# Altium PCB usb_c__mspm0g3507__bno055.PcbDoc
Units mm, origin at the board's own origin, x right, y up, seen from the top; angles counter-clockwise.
Board outline 68 x 40 mm, 2 copper layers (Top, Bottom), stack 0 mm thick; 44 components, 36 nets, 224 pads, 73 vias.
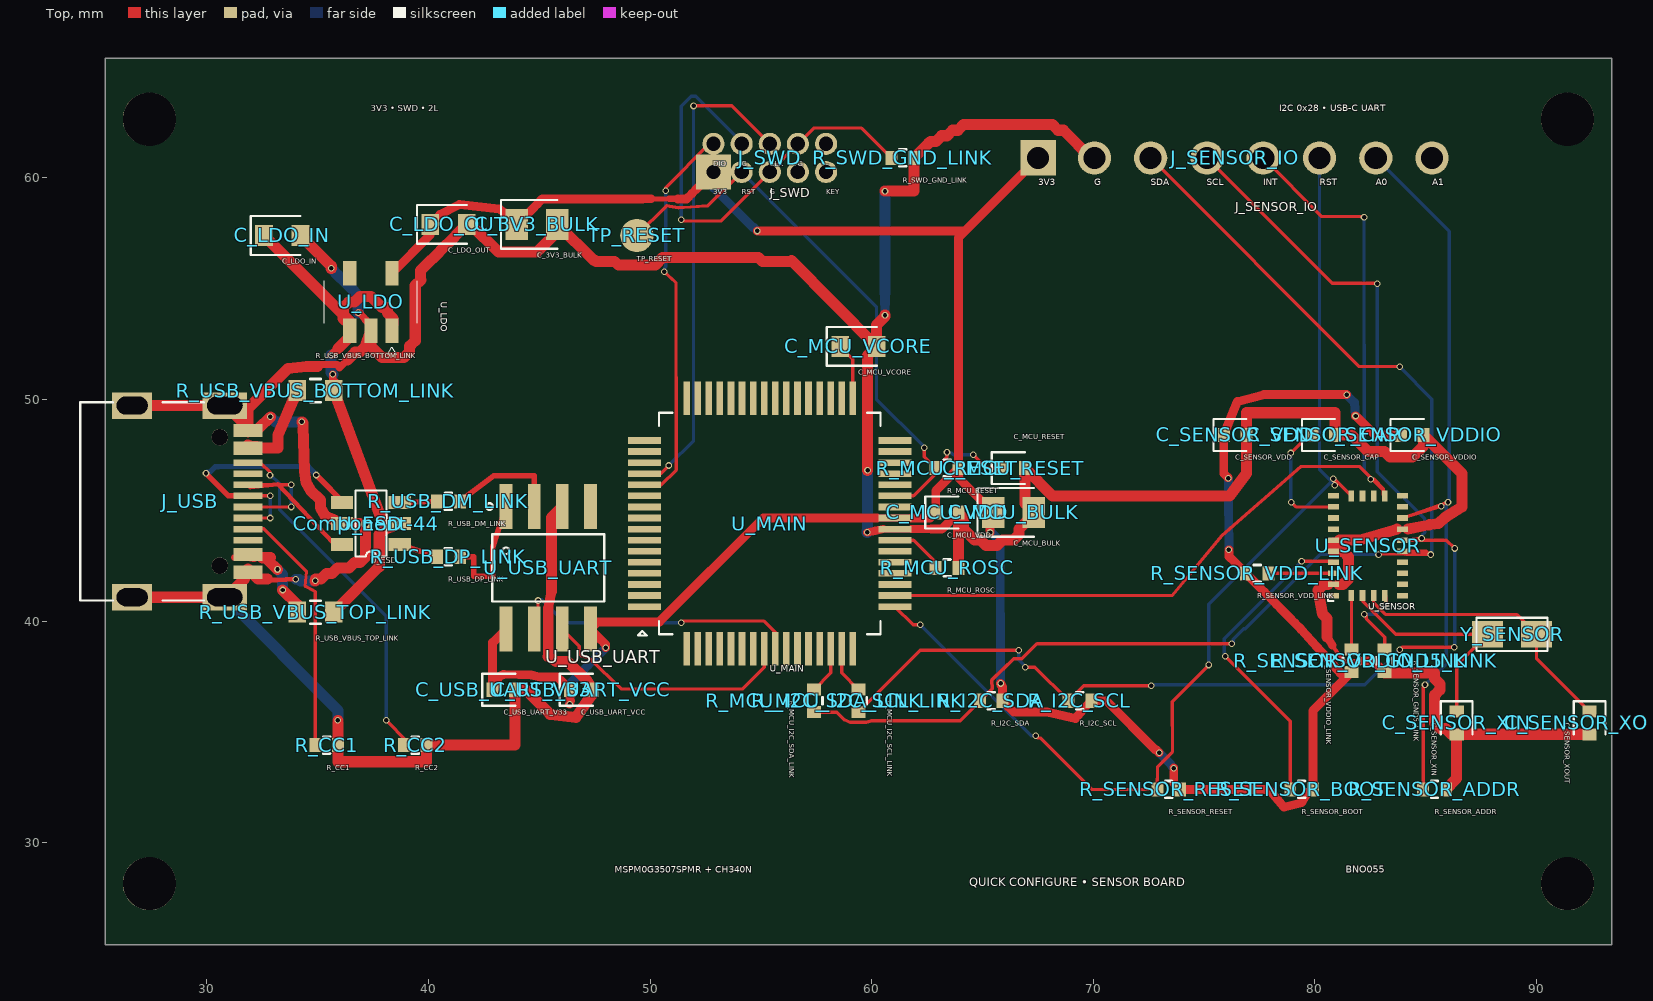
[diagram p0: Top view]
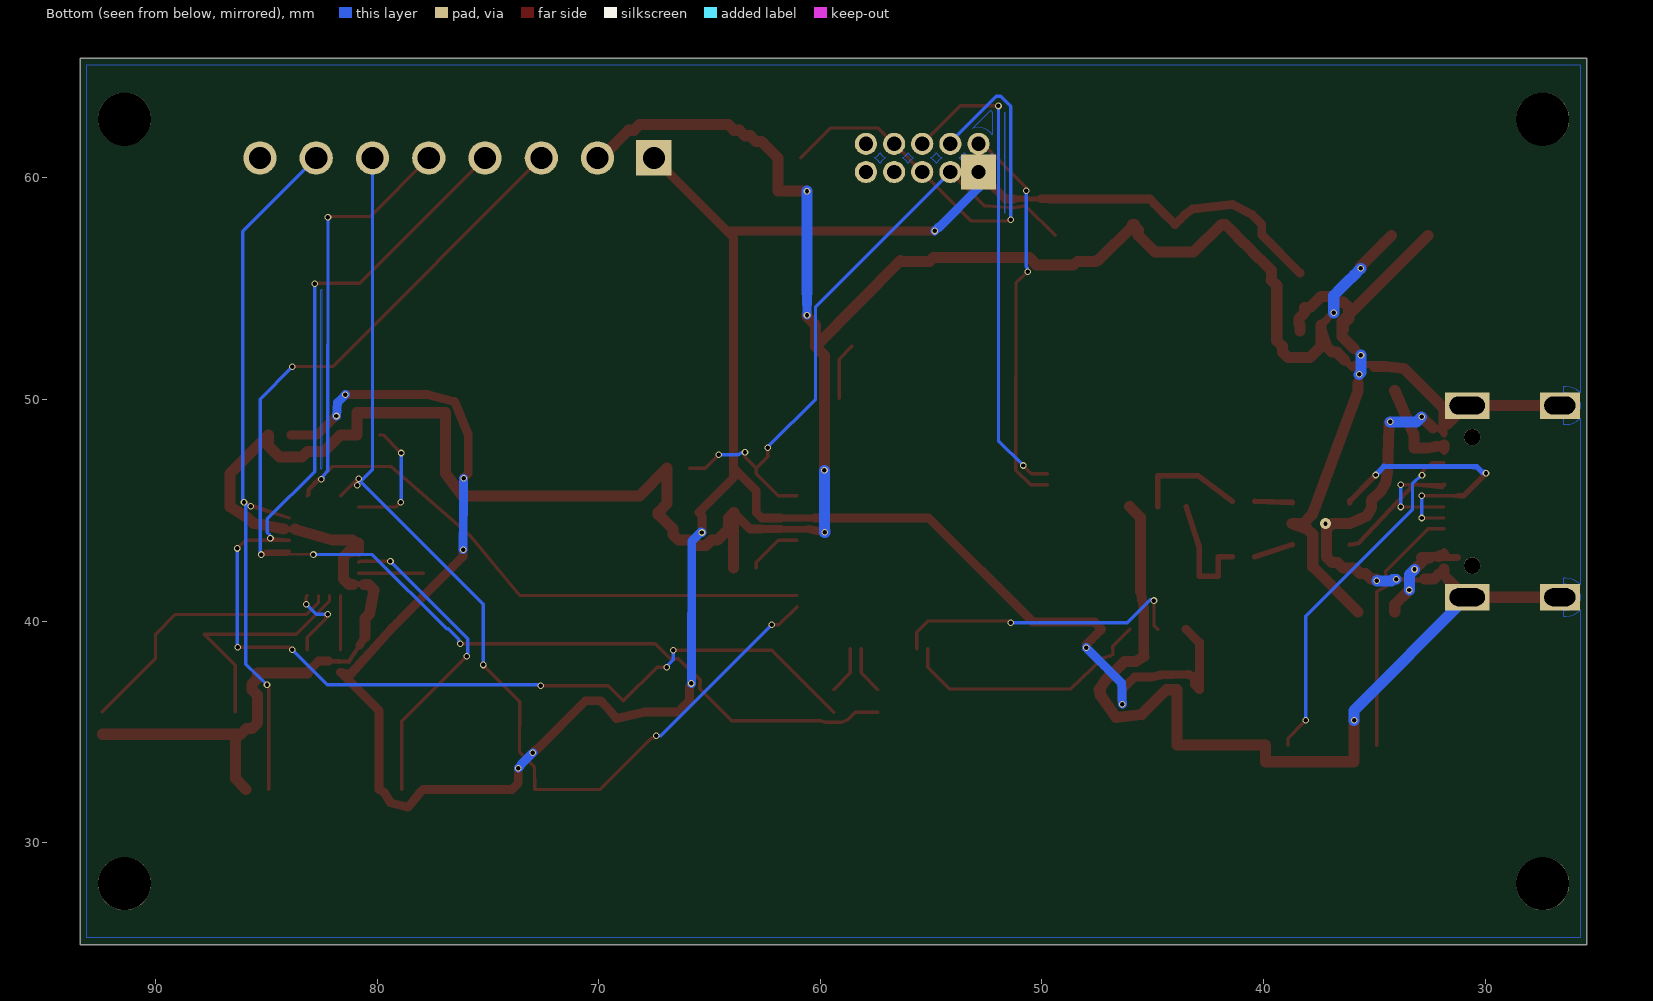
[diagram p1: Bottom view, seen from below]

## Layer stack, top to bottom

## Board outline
25.4,65.4 93.4,65.4 93.4,25.4 25.4,25.4

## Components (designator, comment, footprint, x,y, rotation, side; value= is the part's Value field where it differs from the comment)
C_3V3_BULK "" TSCIRCUIT-2.8500x1.4000mm 44.9,57.9 r0 top
C_LDO_IN "" TSCIRCUIT-2.4500x0.9500mm 33.4,57.4 r0 top
C_LDO_OUT "" TSCIRCUIT-2.4500x0.9500mm 40.9,57.9 r0 top
C_MCU_BULK "" TSCIRCUIT-2.8500x1.4000mm 66.4,44.9 r0 top
C_MCU_RESET "" TSCIRCUIT-1.5600x0.6400mm 66.4,46.9 r0 top
C_MCU_VCORE "" TSCIRCUIT-2.4500x0.9500mm 59.4,52.4 r0 top
C_MCU_VDD "" TSCIRCUIT-1.5600x0.6400mm 63.4,44.9 r0 top
C_SENSOR_CAP "" TSCIRCUIT-1.5600x0.6400mm 80.4,48.4 r0 top
C_SENSOR_VDD "" TSCIRCUIT-1.5600x0.6400mm 76.4,48.4 r0 top
C_SENSOR_VDDIO "" TSCIRCUIT-1.5600x0.6400mm 84.4,48.4 r0 top
C_SENSOR_XIN "" TSCIRCUIT-0.6400x1.5600mm 86.4,35.4 r270 top
C_SENSOR_XOUT "" TSCIRCUIT-0.6400x1.5600mm 92.4,35.4 r270 top
C_USB_UART_V33 "" TSCIRCUIT-1.5600x0.6400mm 43.4,36.9 r0 top
C_USB_UART_VCC "" TSCIRCUIT-1.5600x0.6400mm 46.9,36.9 r0 top
Component-44 "" TSCIRCUIT-0.5000x0.5000mm 37.2,44.4 r0 top
J_SENSOR_IO "" TSCIRCUIT-19.2800x1.5000mm 76.4,60.9 r0 top
J_SWD "" TSCIRCUIT-6.0800x2.2700mm 55.4,60.9 r0 top
J_USB "" TSCIRCUIT-6.7732x9.8502mm 29.112,45.4 r90 top
R_CC1 "" TSCIRCUIT-1.5600x0.6400mm 35.4,34.4 r0 top
R_CC2 "" TSCIRCUIT-1.5600x0.6400mm 39.4,34.4 r0 top
R_I2C_SCL "" TSCIRCUIT-1.5600x0.6400mm 69.4,36.4 r0 top
R_I2C_SDA "" TSCIRCUIT-1.5600x0.6400mm 65.4,36.4 r0 top
R_MCU_I2C_SCL_LINK "" TSCIRCUIT-0.6400x1.5600mm 59.4,36.4 r270 top
R_MCU_I2C_SDA_LINK "" TSCIRCUIT-0.6400x1.5600mm 57.4,36.4 r270 top
R_MCU_RESET "" TSCIRCUIT-1.5600x0.6400mm 63.4,46.9 r0 top
R_MCU_ROSC "" TSCIRCUIT-1.5600x0.6400mm 63.4,42.4 r0 top
R_SENSOR_ADDR "" TSCIRCUIT-1.5600x0.6400mm 85.4,32.4 r0 top
R_SENSOR_BOOT "" TSCIRCUIT-1.5600x0.6400mm 79.4,32.4 r0 top
R_SENSOR_GND5_LINK "" TSCIRCUIT-0.6400x1.5600mm 83.15,38.2 r270 top
R_SENSOR_RESET "" TSCIRCUIT-1.5600x0.6400mm 73.4,32.4 r0 top
R_SENSOR_VDD_LINK "" TSCIRCUIT-1.5600x0.6400mm 77.4,42.15 r0 top
R_SENSOR_VDDIO_LINK "" TSCIRCUIT-0.6400x1.5600mm 81.65,38.2 r270 top
R_SWD_GND_LINK "" TSCIRCUIT-1.5600x0.6400mm 61.4,60.9 r0 top
R_USB_DM_LINK "" TSCIRCUIT-1.5600x0.6400mm 40.9,45.4 r0 top
R_USB_DP_LINK "" TSCIRCUIT-1.5600x0.6400mm 40.9,42.9 r0 top
R_USB_VBUS_BOTTOM_LINK "" TSCIRCUIT-2.4500x0.9500mm 34.9,50.4 r0 top
R_USB_VBUS_TOP_LINK "" TSCIRCUIT-2.4500x0.9500mm 34.9,40.4 r0 top
TP_RESET "" TSCIRCUIT-1.5000x1.5000mm 49.4,57.4 r0 top
U_ESD "" TSCIRCUIT-3.6000x2.5000mm 37.4,44.4 r0 top
U_LDO "" TSCIRCUIT-2.5000x3.7000mm 37.4,54.4 r270 top
U_MAIN "" TSCIRCUIT-12.8000x12.8000mm 55.4,44.4 r0 top
U_SENSOR "" TSCIRCUIT-3.6260x4.9999mm 82.4,43.4 r0 top
U_USB_UART "" TSCIRCUIT-4.3840x7.5712mm 45.4,42.4 r0 top
Y_SENSOR "" TSCIRCUIT-3.6000x1.2000mm 88.9,39.4 r0 top

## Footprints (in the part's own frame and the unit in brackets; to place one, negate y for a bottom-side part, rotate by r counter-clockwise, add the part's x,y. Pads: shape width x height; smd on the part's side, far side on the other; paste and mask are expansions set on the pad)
TSCIRCUIT-0.5000x0.5000mm [mm]
TSCIRCUIT-0.6400x1.5600mm [mm]
  rect 0.54x0.64 smd: 1(-0.51,0) 2(0.51,0)
  silkscreen extent -0.98,-0.72 0.51,0.72
TSCIRCUIT-1.5000x1.5000mm [mm]
  round 1.5 smd: 1(0,0)
TSCIRCUIT-1.5600x0.6400mm [mm]
  rect 0.54x0.64 smd: 1(-0.51,0) 2(0.51,0)
  silkscreen extent -0.98,-0.72 0.51,0.72
TSCIRCUIT-2.4500x0.9500mm [mm]
  rect 0.8x0.95 smd: 1(-0.825,0) 2(0.825,0)
  silkscreen extent -1.42,-0.87 0.82,0.87
TSCIRCUIT-2.5000x3.7000mm [mm]
  rect 1.1x0.6 smd: 1(1.3,0.95) 2(1.3,0) 3(1.3,-0.95) 4(-1.3,-0.95) 5(-1.3,0.95)
  silkscreen extent -0.95,-2.1 2.35,2.1
TSCIRCUIT-2.8500x1.4000mm [mm]
  rect 1.025x1.4 smd: 1(-0.913,0) 2(0.913,0)
  silkscreen extent -1.62,-1.1 0.91,1.1
TSCIRCUIT-3.6000x1.2000mm [mm]
  rect 1.4x1.2 smd: 1(-1.1,0) 2(1.1,0)
  silkscreen extent -1.6,-0.75 1.6,0.75
TSCIRCUIT-3.6000x2.5000mm [mm]
  rect 1x0.6 smd: 1(-1.3,-0.95) 2(-1.3,0) 3(-1.3,0.95) 4(1.3,0.95) 5(1.3,0) 6(1.3,-0.95)
  silkscreen extent -0.7,-1.49 0.7,1.49
TSCIRCUIT-3.6260x4.9999mm [mm]
  rect 0.5x0.25 smd: 1(-1.563,-2.25) 2(-1.563,-1.75) 3(-1.563,-1.25) 4(-1.563,-0.75) 5(-1.563,-0.25) 6(-1.563,0.25) 7(-1.563,0.75) 8(-1.563,1.25) 9(-1.563,1.75) 10(-1.563,2.25) 15(1.563,2.25) 16(1.563,1.75) 17(1.563,1.25) 18(1.563,0.75) 19(1.563,0.25) 20(1.563,-0.25) 21(1.563,-0.75) 22(1.563,-1.25) 23(1.563,-1.75) 24(1.563,-2.25)
  rect 0.25x0.5 smd: 11(-0.75,2.25) 12(-0.25,2.25) 13(0.25,2.25) 14(0.75,2.25) 25(0.75,-2.25) 26(0.25,-2.25) 27(-0.25,-2.25) 28(-0.75,-2.25)
  silkscreen extent -1.81,-2.5 -1.56,-2.25
TSCIRCUIT-4.3840x7.5712mm [mm]
  rect 0.574x2.036 smd: 1(-1.905,2.768) 2(-0.635,2.768) 3(0.635,2.768) 4(1.905,2.768) 5(1.905,-2.768) 6(0.635,-2.768) 7(-0.635,-2.768) 8(-1.905,-2.768)
  silkscreen extent -2.79,-1.52 2.53,2.92
TSCIRCUIT-6.0800x2.2700mm [mm]
  rect 1.6x1.6 hole 0.65: 1(-2.54,-0.635)
  round 1 hole 0.65: 2(-2.54,0.635) 3(-1.27,0.635) 4(0,0.635) 5(1.27,0.635) 6(2.54,0.635) 7(2.54,-0.635) 8(1.27,-0.635) 9(0,-0.635) 10(-1.27,-0.635)
TSCIRCUIT-6.7732x9.8502mm [mm]
  rect 0.3x1.3 smd: 1(-3.35,-2.737) 2(-3.05,-2.737) 3(-2.55,-2.737) 4(-2.25,-2.737) 5(-1.75,-2.737) 6(-1.25,-2.737) 7(-0.75,-2.737) 8(-0.25,-2.737) 9(0.25,-2.737) 10(0.75,-2.737) 11(1.25,-2.737) 12(1.75,-2.737) 13(2.55,-2.737) 14(2.25,-2.737) 15(3.35,-2.737) 16(3.05,-2.737)
  rect 1.2x2 hole 0.8 slot 1.6 at 90 deg: 17(-4.325,-1.693) 18(4.325,-1.693)
  rect 1.2x1.8 hole 0.8 slot 1.4 at 90 deg: 19(4.325,2.487) 20(-4.325,2.487)
  round 0.75 hole 0.75 unplated: NPTH-1(-2.9,-1.468) NPTH-2(2.9,-1.468)
  silkscreen extent -4.47,-0.75 4.47,4.83
TSCIRCUIT-12.8000x12.8000mm [mm]
  rect 1.5x0.3 smd: 1(-5.65,-3.75) 2(-5.65,-3.25) 3(-5.65,-2.75) 4(-5.65,-2.25) 5(-5.65,-1.75) 6(-5.65,-1.25) 7(-5.65,-0.75) 8(-5.65,-0.25) 9(-5.65,0.25) 10(-5.65,0.75) 11(-5.65,1.25) 12(-5.65,1.75) 13(-5.65,2.25) 14(-5.65,2.75) 15(-5.65,3.25) 16(-5.65,3.75) 33(5.65,3.75) 34(5.65,3.25) 35(5.65,2.75) 36(5.65,2.25) 37(5.65,1.75) 38(5.65,1.25) 39(5.65,0.75) 40(5.65,0.25) 41(5.65,-0.25) 42(5.65,-0.75) 43(5.65,-1.25) 44(5.65,-1.75) 45(5.65,-2.25) 46(5.65,-2.75) 47(5.65,-3.25) 48(5.65,-3.75)
  rect 0.3x1.5 smd: 17(-3.75,5.65) 18(-3.25,5.65) 19(-2.75,5.65) 20(-2.25,5.65) 21(-1.75,5.65) 22(-1.25,5.65) 23(-0.75,5.65) 24(-0.25,5.65) 25(0.25,5.65) 26(0.75,5.65) 27(1.25,5.65) 28(1.75,5.65) 29(2.25,5.65) 30(2.75,5.65) 31(3.25,5.65) 32(3.75,5.65) 49(3.75,-5.65) 50(3.25,-5.65) 51(2.75,-5.65) 52(2.25,-5.65) 53(1.75,-5.65) 54(1.25,-5.65) 55(0.75,-5.65) 56(0.25,-5.65) 57(-0.25,-5.65) 58(-0.75,-5.65) 59(-1.25,-5.65) 60(-1.75,-5.65) 61(-2.25,-5.65) 62(-2.75,-5.65) 63(-3.25,-5.65) 64(-3.75,-5.65)
  silkscreen extent -5.95,-5.05 5,5
TSCIRCUIT-19.2800x1.5000mm [mm]
  rect 1.6x1.6 hole 1: 1(-8.89,0)
  round 1.5 hole 1: 2(-6.35,0) 3(-3.81,0) 4(-1.27,0) 5(1.27,0) 6(3.81,0) 7(6.35,0) 8(8.89,0)

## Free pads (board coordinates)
  round 2.4 hole 2.4 unplated: NPTH-3(27.4,28.15) NPTH-4(91.4,28.15) NPTH-5(27.4,62.65) NPTH-6(91.4,62.65)

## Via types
v1: diameter 0.3, hole 0.2, Top to Bottom, 72 vias
v2: diameter 0.5, hole 0.2, Top to Bottom, 1 vias

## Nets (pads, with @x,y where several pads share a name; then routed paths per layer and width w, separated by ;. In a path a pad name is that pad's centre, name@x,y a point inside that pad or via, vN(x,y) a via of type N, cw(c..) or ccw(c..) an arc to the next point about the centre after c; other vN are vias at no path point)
".J_SWD > .pin2 to .U_MAIN > .pin12": J_SWD.2 U_MAIN.12 | length 17.7
  Top w0.15: U_MAIN.12 50.506,46.15 51.174,46.813 51.169,55.271 v1(50.637,55.757) ; v1(50.703,59.419) 50.7,59.422 50.7,59.556 52.68,61.535 J_SWD.2
  Bottom w0.15: v1(50.637,55.757) 50.659,55.825 50.659,55.938 50.703,55.982 v1(50.703,59.419)
".J_SWD > .pin4 to .U_MAIN > .pin13": J_SWD.4 U_MAIN.13 | length 22.1
  Top w0.15: U_MAIN.13 50.471,46.65 v1(50.834,47.019) ; v1(51.96,63.247) 51.968,63.255 52.112,63.255 53.68,63.255 J_SWD.4
  Bottom w0.15: v1(50.834,47.019) 50.843,47.022 51.96,48.139 v1(51.96,63.247)
".U_MAIN > .pin42 to .R_MCU_ROSC > .pin1": R_MCU_ROSC.1 U_MAIN.42 | length 2.5
  Top w0.15: U_MAIN.42 61.889,43.65 62.89,42.649 R_MCU_ROSC.1
".U_SENSOR > .CAP to .C_SENSOR_CAP > .pin1": C_SENSOR_CAP.1 U_SENSOR.9 | length 5.5
  Top w0.15: v1(78.916,47.583) 78.96,47.627 79.733,48.4 C_SENSOR_CAP.1 ; v1(78.93,45.367) 79.147,45.15 U_SENSOR.9
  Bottom w0.15: v1(78.916,47.583) 78.916,45.583 78.916,45.381 v1(78.93,45.367)
BNO055_GND5_LOCAL: R_SENSOR_GND5_LINK.1 U_SENSOR.25 | length 3.6
  Top w0.15: v1(82.234,40.311) 82.315,40.23 82.315,40.114 83.15,39.278 R_SENSOR_GND5_LINK.1 ; U_SENSOR.25 83.214,41.086 v1(83.2,40.75)
  Bottom w0.15: v1(82.234,40.311) 82.759,40.311 83.161,40.713 83.178,40.713 v1(83.2,40.75)
BNO055_VDD_LOCAL: R_SENSOR_VDD_LINK.2 U_SENSOR.3 | length 2.9
  Top w0.15: R_SENSOR_VDD_LINK.2 U_SENSOR.3@80.837,42.15
BNO055_VDDIO_LOCAL: R_SENSOR_VDDIO_LINK.1 U_SENSOR.28 | length 2.4
  Top w0.15: R_SENSOR_VDDIO_LINK.1 U_SENSOR.28
GND: C_3V3_BULK.2 C_LDO_IN.2 C_LDO_OUT.2 C_MCU_BULK.2 C_MCU_RESET.2 C_MCU_VCORE.2 C_MCU_VDD.2 C_SENSOR_CAP.2 C_SENSOR_VDD.2 C_SENSOR_VDDIO.2 C_SENSOR_XIN.2 C_SENSOR_XOUT.2 C_USB_UART_V33.2 C_USB_UART_VCC.2 J_SENSOR_IO.2 J_USB.1 J_USB.2 J_USB.15 J_USB.16 J_USB.17 J_USB.18 J_USB.19 J_USB.20 R_CC1.2 R_CC2.2 R_MCU_ROSC.2 R_SENSOR_ADDR.2 R_SENSOR_GND5_LINK.2 R_SWD_GND_LINK.2 U_ESD.2 U_LDO.2 U_MAIN.41 U_SENSOR.2 U_SENSOR.5 U_SENSOR.6 U_SENSOR.18 U_USB_UART.3 | length 210.6
  Top w0.188: 80.788,38.91 81.032,38.54 81.275,38.17
  Top w0.2: 81.275,38.17 81.73,38.18
  Top w0.225: 32.729,41.888 32.7,41.85 33.133,41.863 33.567,41.875 v1(34,41.888) ; 81.73,38.18 82.185,38.19
  Top w0.25: U_SENSOR.2@80.587,41.65 U_SENSOR.2 U_SENSOR.2@81.087,41.65 ; U_SENSOR.5 U_SENSOR.5@81.087,43.15 ; 80.837,43.525 U_SENSOR.6 80.931,43.65 81.024,43.65 81.087,43.65 81.118,43.65 ; U_SENSOR.18@83.714,44.15 U_SENSOR.18 ; U_SENSOR.18 U_SENSOR.18@84.15,44.15
  Top w0.275: J_USB.2 J_USB.1@32.077,42.119 ; J_USB.16 J_USB.15@32.103,48.704
  Top w0.3: J_USB.1@31.699,41.9 J_USB.1 J_USB.1@31.849,42.2 ; J_USB.15@31.699,48.9 J_USB.15 ; J_USB.16@31.849,48.6 J_USB.15 ; J_USB.15@31.849,48.9 J_USB.15 ; J_USB.15@32.103,48.704 J_USB.15@32.355,48.704 ; U_MAIN.41@60.525,44.15 60.788,44.15 U_MAIN.41 61.144,44.15 61.238,44.15 61.331,44.15 61.425,44.15 61.519,44.15 61.613,44.15 61.706,44.15 61.8,44.15
  Top w0.325: J_USB.16 J_USB.16@31.849,48.6 ; 35.103,51.572 35.494,51.572 35.884,51.572 35.987,51.435 36.34,51.789 ; v1(36.828,53.91) 36.9,53.916 U_LDO.2@37.157,53.601
  Top w0.339: U_SENSOR.18@84.15,44.15 84.213,44.162
  Top w0.35: 34.978,51.484 35.103,51.572 ; U_LDO.2@37.157,53.601 U_LDO.2@37.4,53.358
  Top w0.375: v1(59.8,44) 60.163,44.075 U_MAIN.41@60.525,44.15 ; 61.8,44.15 62.253,44.15 62.707,44.15 ; 80.544,39.28 80.788,38.91
  Top w0.4: 36.6,44.4 37.2,44.4 ; 62.707,44.15 63.16,44.15 63.41,44.4 63.66,44.65 C_MCU_VDD.2 ; 82.185,38.19 82.64,38.2 82.895,37.945 R_SENSOR_GND5_LINK.2
  Top w0.45: 45.4,40.588 45.473,40.959 45.545,41.331
  Top w0.475: 45.4,38.4 45.4,38.837 45.4,39.275 45.4,39.713 45.4,40.15 45.4,40.588
  Top w0.5: J_USB.20 J_USB.17 ; J_USB.19 J_USB.18 ; J_USB.17 30.874,41.075 31.474,41.675 31.699,41.9 ; J_USB.18 30.874,49.725 31.474,49.125 31.699,48.9 ; J_USB.1@31.849,42.2 J_USB.2 ; 31.849,48.9 31.849,49.599 33.65,51.4 34.494,51.482 34.978,51.484 ; J_USB.1@32.077,42.119 32.305,41.888 32.729,41.888 ; J_USB.15@32.355,48.704 v1(32.863,49.212) ; C_LDO_IN.2 34.571,57.054 34.917,56.708 35.263,56.362 35.609,56.016 v1(35.609,55.917) ; v1(34.284,48.989) 34.331,48.942 34.331,48.807 34.4,46.775 34.462,46.275 34.681,45.892 35.119,45.455 35.119,45.127 35.338,44.744 35.719,44.572 U_ESD.2 36.9,44.4 37.15,44.15 37.15,42.9 36.9,42.65 36.65,42.65 36.4,42.4 35.9,42.4 35.65,42.15 35.4,42.15 35.15,41.9 34.9,41.9 34.9,41.832 v1(34.885,41.817) ; v1(35.91,35.52) 35.91,35.4 R_CC1.2 35.91,33.65 39.91,33.65 R_CC2.2 43.91,34.4 C_USB_UART_V33.2 44.385,36.9 45.495,35.79 46.65,35.65 47.364,36.666 47.364,36.854 C_USB_UART_VCC.2 47.15,37.306 46.275,38.181 45.75,38.181 45.4,38.4 ; 36.34,51.789 36.694,52.142 36.9,52.15 37.15,52.4 U_LDO.2 ; U_LDO.2@37.4,53.358 U_LDO.2 ; 45.545,41.331 45.545,41.81 45.545,42.288 45.545,42.766 45.545,43.244 45.545,43.722 45.545,44.2 45.545,44.678 45.79,44.923 U_USB_UART.3 ; v1(59.813,46.799) 59.816,46.802 59.816,46.82 59.816,47.29 59.816,47.76 59.816,48.23 59.816,48.7 59.816,49.17 59.816,49.64 59.816,50.11 59.816,50.58 59.816,51.05 59.816,51.521 59.816,51.991 60.02,52.195 C_MCU_VCORE.2 ; v1(60.6,53.8) 60.6,53.744 60.413,53.557 60.225,53.369 60.225,52.885 C_MCU_VCORE.2 ; v1(60.6,59.4) 61.91,59.4 R_SWD_GND_LINK.2 62.241,61.231 62.571,61.561 62.65,61.64 62.65,61.65 62.9,61.65 63.15,61.9 63.4,61.9 63.65,62.15 63.9,62.15 64.15,62.4 68.15,62.4 68.4,62.15 68.65,62.15 69.9,60.9 J_SENSOR_IO.2 ; R_MCU_ROSC.2 C_MCU_VDD.2 63.9,44.9 64.15,44.65 64.15,44.15 64.65,43.65 64.9,43.65 65.15,43.4 65.65,43.4 65.9,43.65 66.4,43.65 66.65,43.9 66.65,44.15 67.312,44.813 C_MCU_BULK.2 66.91,45.303 C_MCU_RESET.2 68.16,45.65 76.15,45.65 76.919,46.663 76.917,47.097 76.915,47.531 76.912,47.966 C_SENSOR_VDD.2 76.91,49.4 80.91,49.4 C_SENSOR_CAP.2 81.65,48.4 82.4,47.65 83.15,47.65 83.4,47.4 84.4,47.4 84.91,47.91 C_SENSOR_VDDIO.2 86.65,46.66 86.65,45.15 85.885,44.676 85.589,44.411 85.183,44.345 84.213,44.162 ; 80.544,39.28 80.544,40.111 80.336,40.318 80.15,41.4 80.4,41.65 80.587,41.65 ; U_SENSOR.5 80.837,43.275 80.837,43.525 ; 81.087,41.65 81.275,41.65 81.525,41.9 81.525,42.9 81.275,43.15 81.087,43.15 ; 81.118,43.65 81.212,43.65 81.306,43.65 81.399,43.65 81.493,43.65 81.587,43.65 81.994,43.65 U_SENSOR.18@83.713,44.149 ; R_SENSOR_GND5_LINK.2 83.15,37.65 85.4,37.65 85.4,37.4 85.65,37.15 85.65,36.9 85.4,36.65 85.4,35.4 85.65,35.15 85.9,35.15 86.16,34.89 C_SENSOR_XIN.2 ; R_SENSOR_ADDR.2 86.4,32.89 C_SENSOR_XIN.2 ; C_SENSOR_XOUT.2 C_SENSOR_XIN.2 ; U_LDO.2 37.4,52.4 37.9,51.9 38.9,51.9 39.15,52.15 39.15,52.4 39.4,52.65 39.4,55.15 39.65,55.4 39.65,55.39 39.635,55.375 39.635,55.81 39.983,56.158 40.332,56.507 40.68,56.855 41.028,57.203 41.377,57.552 C_LDO_OUT.2 41.9,57.9 43.15,56.65 44.9,56.65 45.65,57.4 45.65,57.65 45.9,57.9 C_3V3_BULK.2 47.465,56.277 47.523,56.277 47.567,56.233 48.4,56.233 48.567,56.067 50.233,56.067 50.567,56.4 54.9,56.4 55.067,56.233 56.4,56.233 56.378,56.256 56.378,56.264 C_MCU_VCORE.2
  Bottom w0.4: v1(60.6,53.8) 60.6,54.291
  Bottom w0.437: 60.6,54.291 60.6,54.781
  Bottom w0.45: v1(34,41.888) v1@34.015,41.879
  Bottom w0.475: v1@34.015,41.879 34.161,41.879
  Bottom w0.5: J_USB.17 35.91,35.971 v1(35.91,35.52) ; v1(32.863,49.212) 32.867,49.208 32.876,49.208 33.095,48.989 33.491,48.989 33.888,48.989 v1(34.284,48.989) ; 34.161,41.879 34.226,41.814 34.555,41.816 v1(34.885,41.817) ; v1(35.609,55.917) 35.619,55.907 35.921,55.605 36.224,55.302 36.526,55 36.828,54.698 36.828,54.304 v1(36.828,53.91) ; v1(59.8,44) 59.8,44.056 59.813,44.069 59.813,44.524 59.813,44.979 59.813,45.434 59.813,45.889 59.813,46.344 v1(59.813,46.799) ; 60.6,54.781 60.6,55.272 60.6,55.763 60.6,56.254 60.6,56.744 60.6,57.235 60.6,57.726 60.6,58.216 60.6,58.707 60.6,59.198 v1(60.6,59.4)
MAIN_RESET: C_MCU_RESET.1 J_SWD.10 R_MCU_RESET.1 TP_RESET.1 U_MAIN.38 | length 29.1
  Top w0.15: TP_RESET.1 50.744,58.744 51.277,58.653 51.833,58.682 52.593,58.744 52.609,58.744 J_SWD.10 ; U_MAIN.38 61.889,45.65 62.89,46.651 R_MCU_RESET.1 ; v1(62.378,47.818) 62.378,47.412 R_MCU_RESET.1 ; v1(63.4,47.62) 63.4,47.41 R_MCU_RESET.1 ; v1(64.583,47.507) 64.625,47.465 65.19,46.9 C_MCU_RESET.1
  Bottom w0.15: J_SWD.10 60.216,54.179 60.216,50.036 60.216,50.015 62.32,47.911 62.32,47.876 v1(62.378,47.818) ; v1(63.4,47.62) 63.438,47.582 63.615,47.582 63.69,47.507 v1(64.583,47.507)
MCU_I2C_SCL_LOCAL: R_MCU_I2C_SCL_LINK.1 U_MAIN.50 | length 2.2
  Top w0.15: U_MAIN.50 58.65,37.66 R_MCU_I2C_SCL_LINK.1
MCU_I2C_SDA_LOCAL: R_MCU_I2C_SDA_LINK.1 U_MAIN.51 | length 2.2
  Top w0.15: R_MCU_I2C_SDA_LINK.1 58.15,37.66 U_MAIN.51
MSPM0_VCORE: C_MCU_VCORE.1 U_MAIN.32 | length 2.6
  Top w0.15: C_MCU_VCORE.1 59.15,51.825 U_MAIN.32
SENSOR_ADDR0: J_SENSOR_IO.7 R_SENSOR_ADDR.1 U_SENSOR.17 | length 34.5
  Top w0.15: R_SENSOR_ADDR.1 84.89,37.005 84.992,37.107 v1(84.972,37.122) ; v1(85.7,45.175) U_SENSOR.17 v1(86.008,45.362)
  Bottom w0.15: J_SENSOR_IO.7 86.067,57.583 86.067,45.496 86.067,45.421 v1(86.008,45.362) ; v1(84.972,37.122) 85.929,38.044 85.929,45.241 85.929,45.283 v1(85.7,45.175)
SENSOR_ADDR1: J_SENSOR_IO.8
SENSOR_BOOT: R_SENSOR_BOOT.1 U_SENSOR.4 | length 14.4
  Top w0.15: v1(75.961,38.418) 76.117,38.262 76.117,38.251 78.89,35.478 R_SENSOR_BOOT.1 ; v1(79.4,42.7) 80.787,42.7 U_SENSOR.4
  Bottom w0.15: v1(75.961,38.418) 75.913,38.464 75.91,39.148 75.915,39.198 79.385,42.669 79.385,42.685 v1(79.4,42.7)
SENSOR_INT: J_SENSOR_IO.5 U_MAIN.47 U_SENSOR.14 | length 43.9
  Top w0.15: U_MAIN.47 73.557,41.15 75.796,43.856 79.386,46.978 82.013,46.978 83.118,45.873 83.118,45.682 U_SENSOR.14 83.094,45.706 83.094,45.974 82.674,46.394 v1(82.52,46.394) ; J_SENSOR_IO.5 80.314,58.256 82.075,58.256 82.177,58.256 v1(82.22,58.216)
  Bottom w0.15: v1(82.22,58.216) 82.23,46.777 82.436,46.558 82.436,46.478 v1(82.52,46.394)
SENSOR_RESET: J_SENSOR_IO.6 R_SENSOR_RESET.1 U_MAIN.48 U_SENSOR.11 | length 50.2
  Top w0.15: U_MAIN.48 61.871,39.829 v1(62.189,39.829) ; v1(67.4,34.82) 67.495,34.725 67.603,34.725 69.929,32.4 R_SENSOR_RESET.1 72.899,33.431 73.578,34.109 73.568,36.363 75.163,37.958 75.163,37.964 v1(75.218,38.019) ; v1(80.833,46.422) v1@80.878,46.422 ; v1(80.9,46.125) v1@80.878,46.422 ; v1@80.878,46.422 U_SENSOR.11 v1@80.878,46.422
  Bottom w0.15: v1(62.189,39.829) 62.216,39.802 67.198,34.82 v1(67.4,34.82) ; v1(75.218,38.019) 75.218,40.76 80.79,46.332 80.79,46.379 v1(80.833,46.422) ; J_SENSOR_IO.6 80.21,46.823 80.686,46.347 80.758,46.347 v1(80.9,46.125)
SENSOR_SCL: J_SENSOR_IO.4 R_I2C_SCL.1 R_MCU_I2C_SCL_LINK.2 U_SENSOR.19 | length 60.6
  Top w0.15: R_MCU_I2C_SCL_LINK.2 62.192,38.682 66.616,38.682 66.63,38.682 v1(66.632,38.68) ; v1(66.924,37.92) 67.37,37.92 R_I2C_SCL.1 69.577,37.087 v1(72.609,37.087) ; J_SENSOR_IO.4 80.782,55.248 82.789,55.248 v1(82.817,55.22) ; v1(83.825,38.7) 83.833,38.7 83.943,38.81 v1(86.285,38.81) ; v1(84.815,43.741) U_SENSOR.19 85.937,43.65 86.309,43.278 v1(86.311,43.276)
  Bottom w0.15: v1(66.632,38.68) 66.632,38.257 66.862,38.026 66.862,37.982 v1(66.924,37.92) ; v1(72.609,37.087) 72.642,37.12 72.733,37.12 82.245,37.12 v1(83.825,38.7) ; v1(82.817,55.22) 82.817,46.741 84.953,44.606 84.953,43.994 84.856,43.897 84.856,43.811 v1(84.815,43.741) ; v1(86.285,38.81) 86.311,38.836 86.311,39.026 v1(86.311,43.276)
SENSOR_SDA: J_SENSOR_IO.3 R_I2C_SDA.1 R_MCU_I2C_SDA_LINK.2 U_SENSOR.20 | length 58.3
  Top w0.15: R_MCU_I2C_SDA_LINK.2 58.417,35.89 58.758,35.548 59.032,35.43 59.3,35.43 59.55,35.429 59.764,35.43 60,35.502 59.987,35.502 63.992,35.502 R_I2C_SDA.1 65.436,36.947 65.418,37.339 66.414,38.304 66.778,38.301 67.458,38.981 v1(76.25,38.981) ; J_SENSOR_IO.3 82.004,51.486 83.765,51.486 83.808,51.486 v1(83.824,51.47) ; v1(82.875,43) 85.2,43.025 85.161,43.025 85.036,43.15 U_SENSOR.20 84.112,43.001 v1(85.224,43.001)
  Bottom w0.15: v1(76.25,38.981) 76.311,39.048 76.311,39.175 76.786,39.65 76.864,39.65 80.215,43.001 v1(82.875,43) ; v1(83.824,51.47) 85.274,50.02 85.274,43.149 85.274,43.051 v1(85.224,43.001)
SENSOR_XIN: C_SENSOR_XIN.1 U_SENSOR.27 Y_SENSOR.1 | length 10.6
  Top w0.15: U_SENSOR.27 82.154,41.146 82.154,40.902 83.656,39.4 Y_SENSOR.1 86.4,38 C_SENSOR_XIN.1
SENSOR_XOUT: C_SENSOR_XOUT.1 U_SENSOR.26 Y_SENSOR.2 | length 12.7
  Top w0.15: U_SENSOR.26 82.649,40.836 83.187,40.298 89.101,40.299 Y_SENSOR.2 90,38.31 C_SENSOR_XOUT.1
swd-ground-1-to-2: J_SWD.3 J_SWD.5 J_SWD.9 R_SWD_GND_LINK.1 | length 20.8
  Top w0.15: v1(51.402,58.115) 51.464,58.053 51.566,58.053 53.188,58.053 J_SWD.9 J_SWD.5 57.382,62.247 59.375,62.247 59.543,62.247 R_SWD_GND_LINK.1
  Bottom w0.15: v1(51.402,58.115) 51.402,63.235 51.847,63.679 52.066,63.679 54.011,61.734 54.011,61.654 J_SWD.3
UART_MSP_RX: U_MAIN.57 U_USB_UART.6 | length 11.7
  Top w0.15: U_USB_UART.6 46.807,38.86 46.791,38.493 46.894,38.439 47.248,38.324 48.711,36.929 54.165,36.929 55.15,37.914 U_MAIN.57
UART_MSP_TX: U_MAIN.56 U_USB_UART.7 | length 13.5
  Top w0.15: U_USB_UART.7 44.943,39.81 v1(44.943,40.924) ; v1(51.408,39.926) 51.413,39.931 51.421,39.931 51.491,40 55.142,40 55.65,39.492 U_MAIN.56
  Bottom w0.15: v1(44.943,40.924) 44.994,40.975 45.094,40.975 46.144,39.926 v1(51.408,39.926)
usb-dm-device: R_USB_DM_LINK.1 U_ESD.4 | length 1.7
  Top w0.25: U_ESD.4 R_USB_DM_LINK.1
usb-dm-port-tie: J_USB.7 J_USB.9 U_ESD.3 | length 12.4
  Top w0.15: J_USB.9@31.349,45.65 31.38,45.65 31.474,45.65 31.568,45.65 31.662,45.65 31.615,45.65 J_USB.9 v1(32.85,45.65) ; J_USB.7 v1(32.85,44.65)
  Top w0.175: J_USB.9@31.287,45.65 J_USB.9@31.349,45.65
  Top w0.212: 31.193,45.65 J_USB.9@31.287,45.65
  Top w0.25: v1(29.956,46.662) 30.968,45.65 31.099,45.65 31.193,45.65 ; v1(34.932,46.591) 35.09,46.433 ; 35.09,46.432 36.1,45.422 U_ESD.3
  Bottom w0.15: v1(32.85,44.65) v1(32.85,45.65)
  Bottom w0.25: v1(29.956,46.662) 30.004,46.71 30.118,46.71 30.365,46.957 30.515,46.972 34.566,46.978 v1(34.932,46.591)
usb-dm-uart: R_USB_DM_LINK.2 U_USB_UART.2 | length 5.1
  Top w0.25: R_USB_DM_LINK.2 42.95,46.55 44.765,46.55 U_USB_UART.2
usb-dp-device: R_USB_DP_LINK.1 U_ESD.6 | length 1.8
  Top w0.25: U_ESD.6 R_USB_DP_LINK.1
usb-dp-port-tie: J_USB.8 J_USB.10 U_ESD.1 | length 10.4
  Top w0.15: J_USB.8 v1(33.8,45.15) ; J_USB.10 v1(33.8,46.15)
  Top w0.2: J_USB.10 31.954,46.045 33.191,46.179 35.713,43.512 U_ESD.1
  Bottom w0.15: v1(33.8,45.15) v1(33.8,46.15)
usb-dp-uart: R_USB_DP_LINK.2 U_USB_UART.1 | length 5.6
  Top w0.25: R_USB_DP_LINK.2 42.05,42.9 42.05,42.03 42.9,42.03 42.9,43.35 U_USB_UART.1
USB_CC1: J_USB.6 R_CC1.1 | length 11.6
  Top w0.15: J_USB.6 31.861,44.162 32.57,44.162 34.49,42.242 34.425,41.575 34.889,41.333 R_CC1.1
USB_CC2: J_USB.12 R_CC2.1 | length 16
  Top w0.15: J_USB.12 32.416,47.151 32.845,46.722 v1(32.844,46.586) ; v1(38.09,35.52) 38.232,35.378 38.89,34.72 R_CC2.1
  Bottom w0.15: v1(32.844,46.586) 32.867,46.6 33.276,46.191 33.276,45.024 38.09,40.21 v1(38.09,35.52)
USB_VBUS_BOTTOM_LOCAL: J_USB.13 J_USB.14 R_USB_VBUS_BOTTOM_LINK.1 | length 4.4
  Top w0.3: J_USB.14 J_USB.14@31.849,47.8
  Top w0.45: J_USB.13 J_USB.13@32.225,47.875
  Top w0.475: J_USB.13@31.849,47.8 J_USB.13
  Top w0.5: J_USB.13@32.225,47.875 32.6,47.8 33.2,47.8 33.2,48.4 R_USB_VBUS_BOTTOM_LINK.1
USB_VBUS_TOP_LOCAL: J_USB.3 J_USB.4 R_USB_VBUS_TOP_LINK.1 | length 7.1
  Top w0.3: J_USB.4 31.849,43 J_USB.3 31.834,42.865 31.24,42.865 31.646,42.865 32.052,42.865 32.458,42.865 J_USB.3@32.499,42.865 ; J_USB.3@32.125,42.904 32.224,42.85 32.349,42.85 32.474,42.85 J_USB.3@32.499,42.85
  Top w0.423: J_USB.3@31.999,42.948 32.432,42.907 32.864,42.865
  Top w0.5: J_USB.3@31.999,42.948 J_USB.3@32.125,42.904 ; 32.499,42.85 32.599,42.85 32.651,42.85 32.703,42.798 32.791,42.71 v1(33.185,42.328) ; 32.499,42.865 32.864,42.865 ; v1(33.415,41.402) 33.44,41.377 34.075,40.742 R_USB_VBUS_TOP_LINK.1
  Bottom w0.5: v1(33.185,42.328) 33.415,42.098 v1(33.415,41.402)
VBUS5: C_LDO_IN.1 R_USB_VBUS_BOTTOM_LINK.2 R_USB_VBUS_TOP_LINK.2 U_ESD.5 U_LDO.1 U_LDO.3 | length 26.2
  Top w0.325: v1(35.6,52) v1@35.633,52.033 ; v1(35.68,51.136) 35.68,50.79 R_USB_VBUS_BOTTOM_LINK.2@35.725,50.745
  Top w0.375: v1@35.633,52.033 35.905,52.305
  Top w0.5: C_LDO_IN.1 36.45,53.525 U_LDO.3 ; R_USB_VBUS_TOP_LINK.2 37.775,42.45 37.775,43.9 38.025,44.15 U_ESD.5 38.2,44.4 37.8,44.8 R_USB_VBUS_BOTTOM_LINK.2 R_USB_VBUS_BOTTOM_LINK.2@35.725,50.745 ; 35.905,52.305 36.178,52.578 36.45,52.85 U_LDO.3 ; U_LDO.1 38.35,53.35 38.4,53.4 38.4,53.65 38.15,53.9 38.15,54.15 37.9,54.15 37.4,54.65 36.9,54.65 36.65,54.4 36.4,54.4 36.15,54.15 36.15,53.65 36.4,53.4 36.4,53.15 U_LDO.3
  Bottom w0.5: v1(35.6,52) 35.6,51.216 v1(35.68,51.136)
VCC_3V3: C_3V3_BULK.1 C_LDO_OUT.1 C_MCU_BULK.1 C_MCU_VDD.1 C_SENSOR_VDD.1 C_SENSOR_VDDIO.1 C_USB_UART_V33.1 C_USB_UART_VCC.1 J_SENSOR_IO.1 J_SWD.1 R_I2C_SCL.2 R_I2C_SDA.2 R_MCU_RESET.2 R_SENSOR_BOOT.2 R_SENSOR_RESET.2 R_SENSOR_VDD_LINK.1 R_SENSOR_VDDIO_LINK.2 U_LDO.5 U_MAIN.40 U_USB_UART.5 U_USB_UART.8 | length 141
  Top w0.225: 50.052,59.052 50.451,59.052 50.85,59.052
  Top w0.288: 50.85,59.052 51.249,59.052
  Top w0.3: 60.25,44.65 60.3,44.65 60.35,44.65 60.45,44.65 60.55,44.65 60.65,44.65 60.75,44.65 60.85,44.65 60.95,44.65 U_MAIN.40 61.15,44.65 61.25,44.65 61.35,44.65 61.45,44.65 61.55,44.65 61.65,44.65 61.75,44.65 61.8,44.65
  Top w0.337: v1@76.074,46.466 v1(76.098,46.442)
  Top w0.387: 49.654,59.052 50.052,59.052
  Top w0.4: U_LDO.5 40.075,57.425 C_LDO_OUT.1 40.296,58.122 40.518,58.343 41.4,58.8 43.2,58.6 43.545,58.343 43.766,58.121 C_3V3_BULK.1 44.218,58.13 44.449,58.361 44.679,58.591 44.91,58.822 45.14,59.052 45.485,59.052 45.829,59.052 46.174,59.052 46.518,59.052 46.863,59.052 47.261,59.052 47.66,59.052 48.059,59.052 48.458,59.052 48.856,59.052 49.255,59.052 49.654,59.052 ; U_USB_UART.8 42.89,39.027 C_USB_UART_V33.1 43.126,37.136 43.126,37.47 43.4,37.6 44.638,37.564 45.05,37.47 45.435,37.47 45.82,37.47 46.01,37.28 46.2,37.09 C_USB_UART_VCC.1 46.39,36.657 46.39,36.414 46.4,36.404 v1(46.369,36.243) ; v1(48,38.8) 48,38.937 47.768,39.169 47.537,39.4 U_USB_UART.5 47.633,39.96 50.419,39.96 55.108,44.65 60.25,44.65 ; 51.249,59.052 51.647,59.052 51.89,59.295 52.132,59.537 52.375,59.78 52.617,60.022 J_SWD.1 ; v1(54.833,57.605) 64.215,57.605 J_SENSOR_IO.1 63.91,57.3 R_MCU_RESET.2 ; 61.8,44.65 61.85,44.65 62.64,44.65 C_MCU_VDD.1 62.89,45.88 R_MCU_RESET.2 ; v1(65.341,43.997) 65.335,44.747 C_MCU_BULK.1 63.91,46.478 R_MCU_RESET.2 ; v1(65.818,37.183) 65.83,37.17 65.826,37.115 65.91,37.032 R_I2C_SDA.2 66.16,36.149 66.409,35.897 66.784,35.896 67.16,35.895 67.535,35.894 67.91,35.892 69.2,35.6 69.66,36.144 R_I2C_SCL.2 70.596,36.4 72.824,34.172 72.854,34.172 v1(72.971,34.055) ; v1(73.631,33.364) 73.631,32.679 R_SENSOR_RESET.2 74.274,32.4 74.638,32.4 75.002,32.4 75.366,32.4 75.73,32.4 76.094,32.4 76.458,32.4 76.821,32.4 77.185,32.4 77.549,32.4 77.913,32.4 78.113,32.199 78.6,31.6 79.4,31.8 79.655,32.24 R_SENSOR_BOOT.2 79.91,35.95 R_SENSOR_VDDIO_LINK.2 81.2,37.6 79.382,39.625 79.105,39.905 78.828,40.186 78.551,40.466 78.274,40.747 77.998,41.028 77.721,41.308 77.444,41.589 77.167,41.869 R_SENSOR_VDD_LINK.1 76.633,42.407 76.377,42.663 76.12,42.92 v1(76.12,43.22) ; v1@76.074,46.466 76.074,46.476 75.89,46.661 75.89,47.008 75.89,47.356 75.89,47.704 75.89,48.052 C_SENSOR_VDD.1 76.5,49.9 77.707,50.217 v1(81.433,50.217) ; v1(81.838,49.253) 81.95,49.157 81.953,49.157 82.71,48.4 C_SENSOR_VDDIO.1
  Bottom w0.4: v1(46.369,36.243) 46.379,36.562 46.39,36.881 46.4,37.2 46.665,37.465 46.93,37.73 47.195,37.995 47.459,38.259 47.724,38.524 47.989,38.789 v1(48,38.8) ; J_SWD.1 52.86,59.547 54.65,57.757 54.681,57.757 v1(54.833,57.605) ; v1(65.341,43.997) 65.378,44.017 65.378,44.024 65.8,43.602 v1(65.818,37.183) ; v1(72.971,34.055) 72.992,34.036 73.518,33.51 73.518,33.477 v1(73.631,33.364) ; v1(76.098,46.442) 76.101,46.064 76.104,45.687 76.106,45.309 76.109,44.931 76.112,44.554 76.115,44.176 76.117,43.799 76.12,43.421 v1(76.12,43.22) ; v1(81.433,50.217) 81.469,50.181 81.791,49.859 v1(81.838,49.253)
pads on no net: J_SWD.6 J_SWD.7 J_SWD.8 J_USB.5 J_USB.11 J_USB.NPTH-1 J_USB.NPTH-2 U_LDO.4 U_MAIN.1 U_MAIN.2 U_MAIN.3 U_MAIN.4 U_MAIN.5 U_MAIN.6 U_MAIN.7 U_MAIN.8 U_MAIN.9 U_MAIN.10 U_MAIN.11 U_MAIN.14 U_MAIN.15 U_MAIN.16 U_MAIN.17 U_MAIN.18 U_MAIN.19 U_MAIN.20 U_MAIN.21 U_MAIN.22 U_MAIN.23 U_MAIN.24 U_MAIN.25 U_MAIN.26 U_MAIN.27 U_MAIN.28 U_MAIN.29 U_MAIN.30 U_MAIN.31 U_MAIN.33 U_MAIN.34 U_MAIN.35 U_MAIN.36 U_MAIN.37 U_MAIN.39 U_MAIN.43 U_MAIN.44 U_MAIN.45 U_MAIN.46 U_MAIN.49 U_MAIN.52 U_MAIN.53 U_MAIN.54 U_MAIN.55 U_MAIN.58 U_MAIN.59 U_MAIN.60 U_MAIN.61 U_MAIN.62 U_MAIN.63 U_MAIN.64 U_SENSOR.1 U_SENSOR.7 U_SENSOR.8 U_SENSOR.10 U_SENSOR.12 U_SENSOR.13 U_SENSOR.15 U_SENSOR.16 U_SENSOR.21 U_SENSOR.22 U_SENSOR.23 U_SENSOR.24 U_USB_UART.4
copper on no net:
  other v2: 37.2,44.4

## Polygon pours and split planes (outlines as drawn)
GND on Bottom (solid): 93.1,65.1 25.7,65.1 25.7,50.296 25.725,50.326 25.854,50.432 26.001,50.51 26.16,50.559 26.326,50.575 26.476,50.575 26.476,50.325 26.326,50.325 26.209,50.314 26.096,50.279 25.993,50.224 25.902,50.149 25.827,50.058 25.772,49.955 25.747,49.875 25.7,49.875 25.7,49.575 25.747,49.575 25.772,49.496 25.827,49.392 25.902,49.301 25.993,49.226 26.096,49.171 26.209,49.137 26.326,49.125 26.476,49.125 26.476,48.875 26.326,48.875 26.16,48.891 26.001,48.94 25.854,49.018 25.725,49.124 25.7,49.154 25.7,41.646 25.725,41.676 25.854,41.782 26.001,41.86 26.16,41.909 26.326,41.925 26.476,41.925 26.476,41.675 26.326,41.675 26.209,41.663 26.096,41.629 25.993,41.574 25.902,41.499 25.827,41.408 25.772,41.304 25.747,41.225 25.7,41.225 25.7,40.925 25.747,40.925 25.772,40.845 25.827,40.742 25.902,40.651 25.993,40.576 26.096,40.521 26.209,40.486 26.326,40.475 26.476,40.475 26.476,40.225 26.326,40.225 26.16,40.241 26.001,40.29 25.854,40.368 25.725,40.474 25.7,40.504 25.7,25.7 93.1,25.7
GND on Bottom (solid): 52.306,63.05 52.293,63.025 52.243,62.964 52.235,62.958 52.235,61.949 52.236,61.952 52.33,62.065 52.443,62.159 52.573,62.228 52.714,62.271 52.86,62.285 53.006,62.271 53.12,62.236
GND on Bottom (solid): 53.495,61.14 53.484,61.118 53.399,61.015 53.591,61.015 53.506,61.118
GND on Bottom (solid): 52.235,61.121 52.235,61.015 52.321,61.015 52.236,61.118
GND on Bottom (solid): 53.61,60.996 53.61,60.804 53.713,60.889 53.735,60.9 53.713,60.911
GND on Bottom (solid): 57.305,61.14 57.294,61.118 57.2,61.005 57.087,60.911 57.065,60.9 57.087,60.889 57.2,60.795 57.294,60.682 57.305,60.66 57.316,60.682 57.41,60.795 57.523,60.889 57.545,60.9 57.523,60.911 57.41,61.005 57.316,61.118
GND on Bottom (solid): 56.035,61.14 56.024,61.118 55.93,61.005 55.817,60.911 55.795,60.9 55.817,60.889 55.93,60.795 56.024,60.682 56.035,60.66 56.046,60.682 56.14,60.795 56.253,60.889 56.275,60.9 56.253,60.911 56.14,61.005 56.046,61.118
GND on Bottom (solid): 54.765,61.14 54.754,61.118 54.66,61.005 54.547,60.911 54.525,60.9 54.547,60.889 54.66,60.795 54.754,60.682 54.765,60.66 54.776,60.682 54.87,60.795 54.983,60.889 55.005,60.9 54.983,60.911 54.87,61.005 54.776,61.118
GND on Bottom (solid): 51.677,62.964 51.677,58.404 51.685,58.398 51.685,62.958 51.677,62.964
GND on Bottom (solid): 82.498,54.981 82.505,46.886 82.542,46.846 82.542,54.931 82.534,54.937

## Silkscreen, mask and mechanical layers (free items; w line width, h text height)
Top Overlay:
  text "3V3 • SWD • 2L" at 37.4,62.9 h0.48
  text "I2C 0x28 • USB-C UART" at 78.4,62.9 h0.5
  text "MSPM0G3507SPMR + CH340N" at 48.4,28.525 h0.52
  text "BNO055" at 81.4,28.525 h0.55
  text "QUICK CONFIGURE • SENSOR BOARD" at 64.4,27.9 h0.65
